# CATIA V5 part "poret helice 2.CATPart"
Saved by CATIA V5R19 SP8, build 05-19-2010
Part number: poret helice 2
Bounding box of the stored display mesh (mm): x -20 to 20, y -50 to 180, z -20 to 20
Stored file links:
  G:\EU_thinkMotion\CFAO_2010\MMS_groupe2\MMS_groupe2\A reprendre\splanchenault\Planchenault\poret helice 2.CATPart
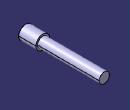
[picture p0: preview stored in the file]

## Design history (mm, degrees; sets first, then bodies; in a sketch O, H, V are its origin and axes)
Body1 (main body)
  Sketch1 on zx-plane, origin (0, 0, 0), H (-1, 0, 0), V (0, 0, 1)
    circle A1 centre (0, 0) radius 15
    radius A1 = 15
  Pad1: profile Sketch1, direction (0, 1, 0), length 180
  Sketch2 on start face of Pad1, origin (0, 0, 0), H (1, 0, 0), V (0, 0, 1)
    circle A1 centre (0, 0) radius 20
    radius A1 = 20
  Pad2: profile Sketch2, direction (0, -1, 0), length 50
